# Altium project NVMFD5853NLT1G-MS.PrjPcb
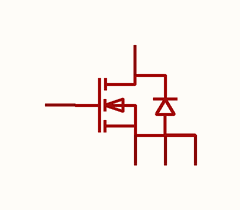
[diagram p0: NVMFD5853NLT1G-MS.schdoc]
1 sheet, 1 parts. Net scope: global (net labels, ports and power ports of the same name join across sheets).

## Sheet NVMFD5853NLT1G-MS.schdoc
size 127 x 101 mm

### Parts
Q?  nvmfd5853nlt1g-ms  [TDSON-8_L5.9-W5.2-P1.27-BL]  (value not drawn)

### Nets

Not connected (* = marked no-connect by the designer): Q? 1(S) 2(S) 3(S) 4(G) 5(D)

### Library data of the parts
Q? = nvmfd5853nlt1g-ms: 数量:1个N沟道;漏源电压(Vdss):40V;连续漏极电流(Id):50A;导通电阻(RDS(on)):11mΩ@10V;阈值电压(Vgs(th)):2.5V;; Manufacturer: MSKSEMI(美森科); AddInBom: yes; ModelId: ff3d8edf19694f3eb1c5df98919f3bc8; ModelTransform: 216.9287,242.5192,0,0,0,0,0,43.307,0; Number: 1个N沟道; Drain to Source Voltage: 40V; Current - Continuous Drain(Id): 50A; Gate Threshold Voltage (Vgs(th)): 2.5V; Gate Charge(Qg): 24nC@10V; Input Capacitance(Ciss): 1.54nF; Reverse Transfer Capacitance (Crss@Vds): 115pF; Type: N沟道; Output Capacitance(Coss): 171pF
